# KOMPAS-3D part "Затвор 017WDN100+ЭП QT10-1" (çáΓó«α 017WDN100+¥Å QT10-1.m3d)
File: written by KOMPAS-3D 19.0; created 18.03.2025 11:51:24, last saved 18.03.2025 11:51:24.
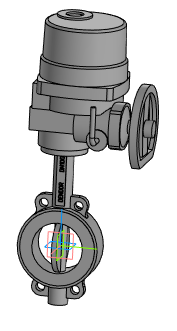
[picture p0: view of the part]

Document properties: Полное имя файла: Затвор 017WDN100+ЭП QT10-1.a3d

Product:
- Part/product: Затвор 017WDN100+ЭП QT10-1
    Масса: 47.6074

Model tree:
1. Операция без истории:1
